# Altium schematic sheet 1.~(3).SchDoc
size 420 x 297 mm
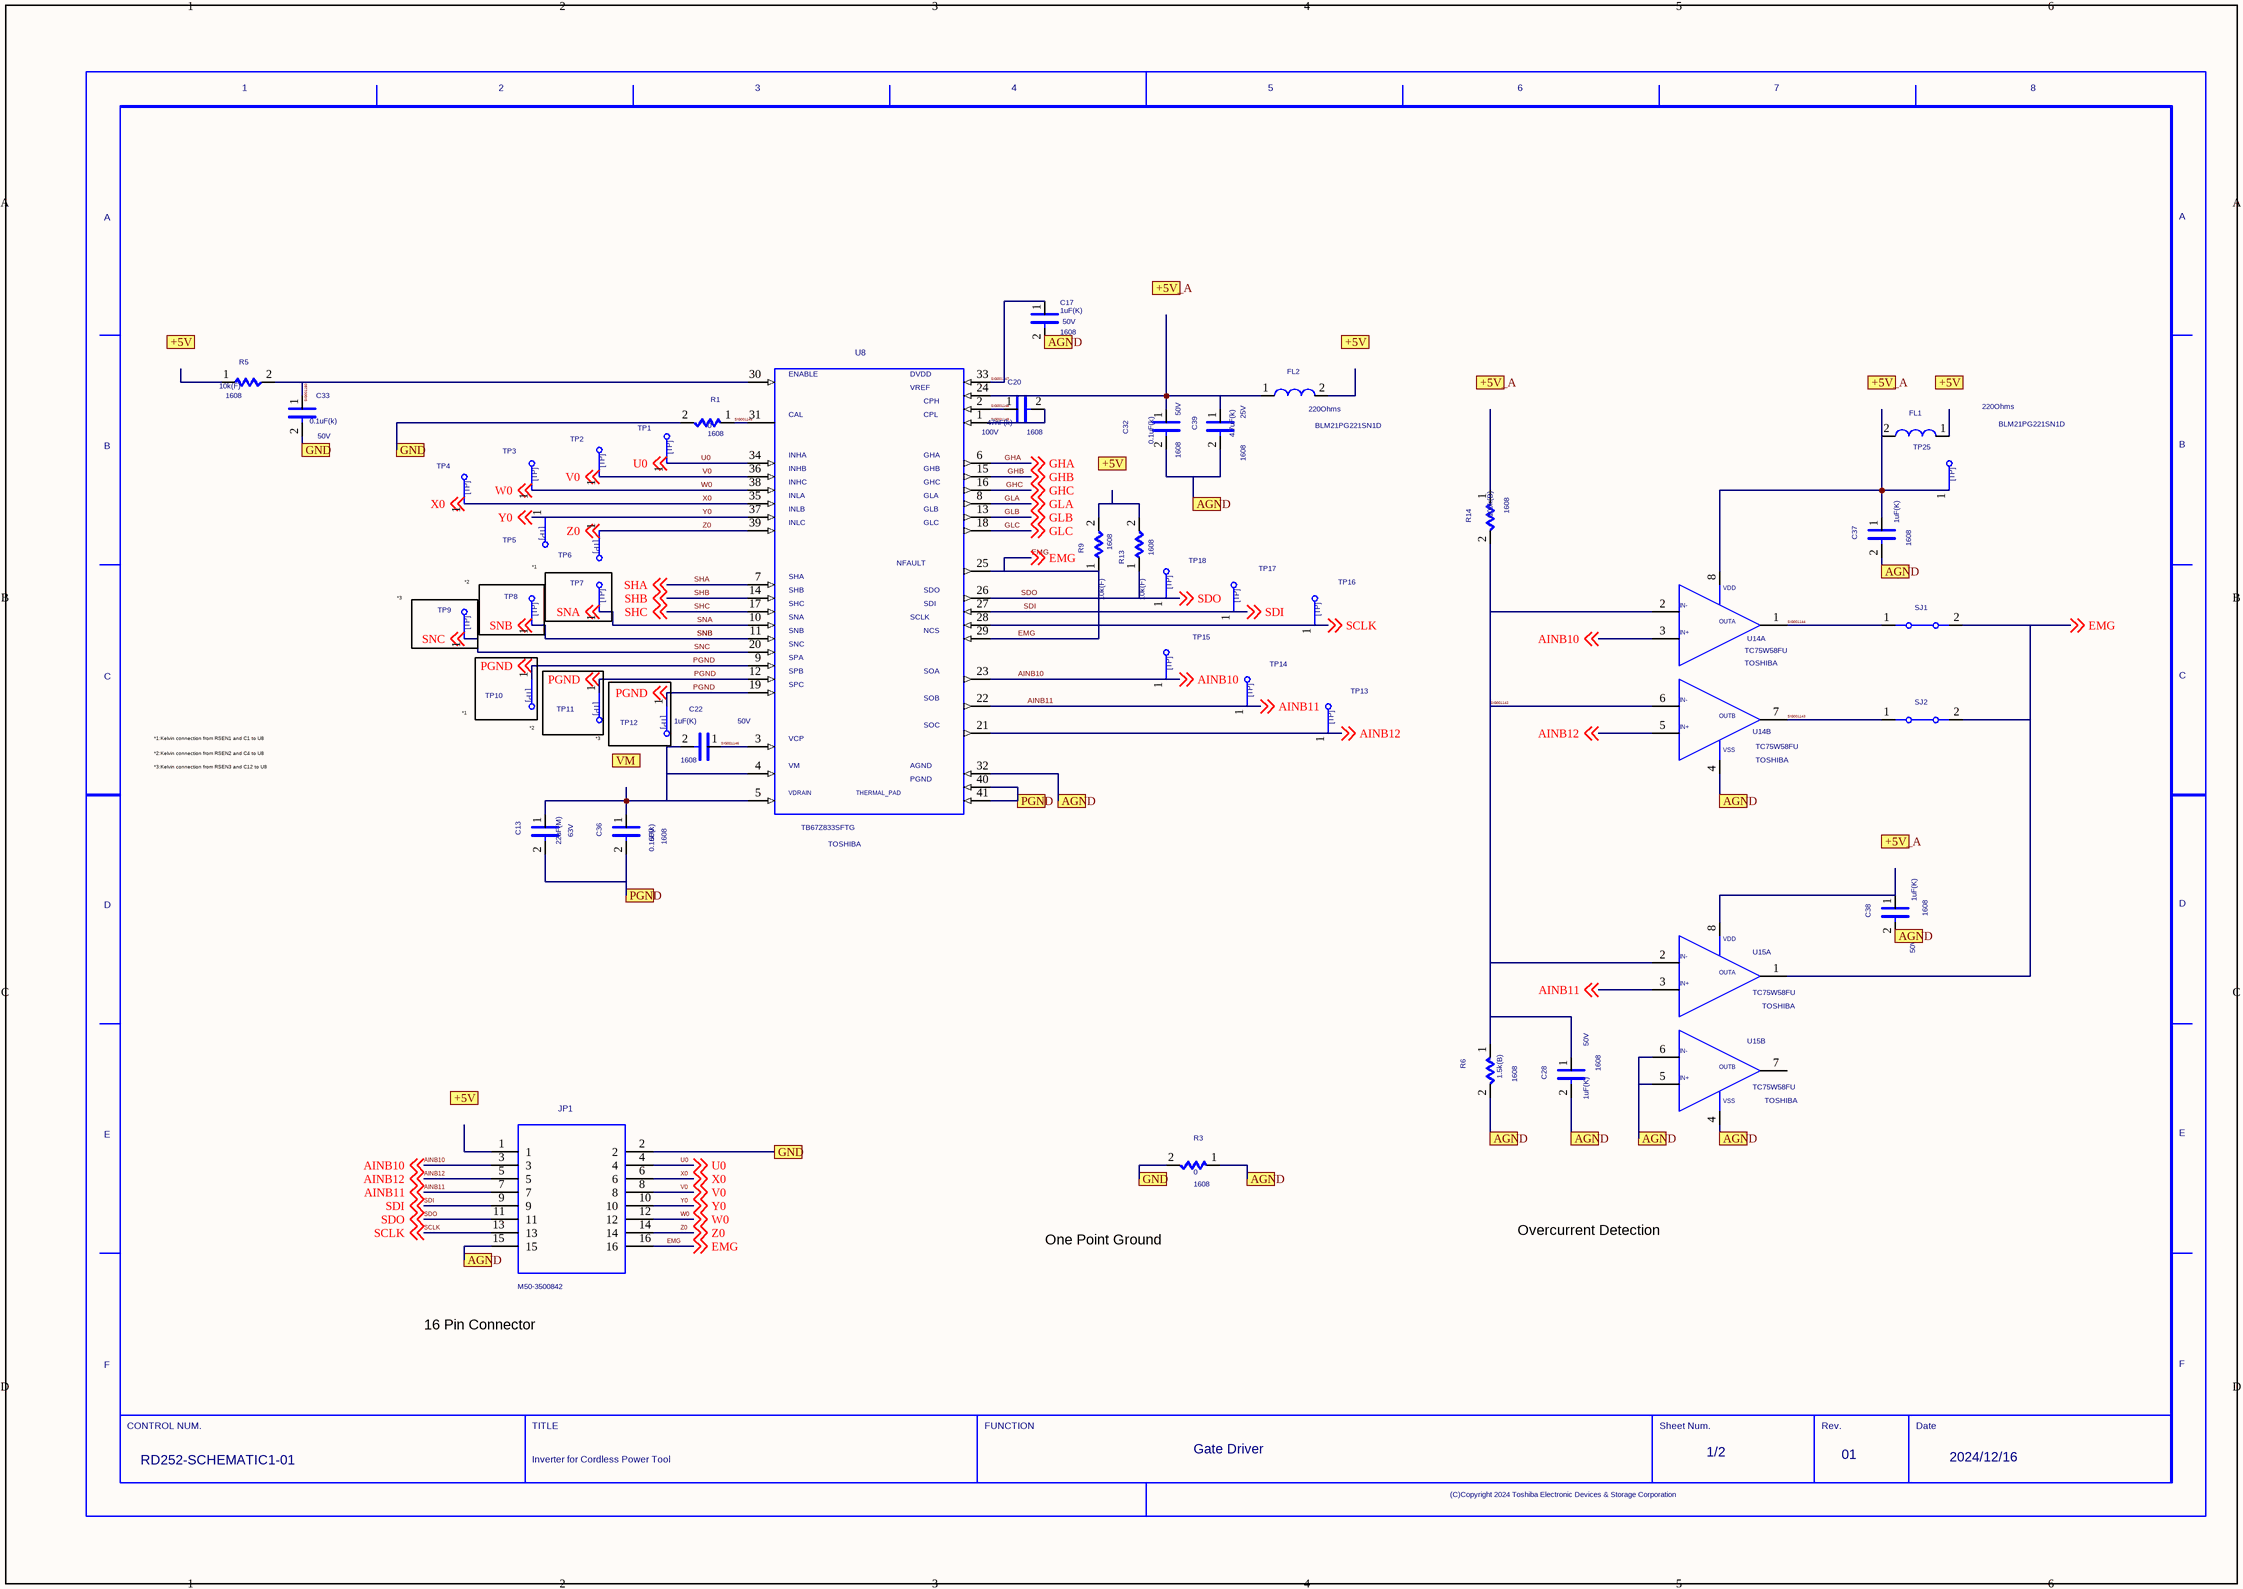
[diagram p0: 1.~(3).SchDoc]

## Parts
C13  VAL2: 63V  VAL1: 22uF(M)  (hidden comment: C)
C17  SIZECODESMD: 1608  VAL2: 50V  VAL1: 1uF(K)  (hidden comment: C)
C20  SIZECODESMD: 1608  VAL2: 100V  VAL1: 47nF(k)  (hidden comment: C)
C22  VAL2: 50V  SIZECODESMD: 1608  VAL1: 1uF(K)  (hidden comment: C)
C28  SIZECODESMD: 1608  VAL2: 50V  VAL1: 1uF(K)  (hidden comment: C)
C32  SIZECODESMD: 1608  VAL2: 50V  VAL1: 0.1uF(k)  (hidden comment: C)
C33  SIZECODESMD: 1608  VAL2: 50V  VAL1: 0.1uF(k)  (hidden comment: C)
C36  SIZECODESMD: 1608  VAL2: 50V  VAL1: 0.1uF(k)  (hidden comment: C)
C37  SIZECODESMD: 1608  VAL2: 50V  VAL1: 1uF(K)  (hidden comment: C)
C38  SIZECODESMD: 1608  VAL2: 50V  VAL1: 1uF(K)  (hidden comment: C)
C39  SIZECODESMD: 1608  VAL2: 25V  VAL1: 4.7uF(k)  (hidden comment: C)
FL1  VAL1: 220Ohms  VAL3: BLM21PG221SN1D  (hidden comment: L)
FL2  VAL1: 220Ohms  VAL3: BLM21PG221SN1D  (hidden comment: L)
JP1  VAL3: M50-3500842  [IDC16_1_27MM]  (hidden comment: CONN_16PINJ)
R1  SIZECODESMD: 1608  VAL1: 0  (hidden comment: R)
R3  SIZECODESMD: 1608  VAL1: 0  (hidden comment: R)
R5  SIZECODESMD: 1608  VAL1: 10k(F)  (hidden comment: R)
R6  SIZECODESMD: 1608  VAL1: 1.5k(B)  (hidden comment: R)
R9  SIZECODESMD: 1608  VAL1: 10k(F)  (hidden comment: R)
R13  SIZECODESMD: 1608  VAL1: 10k(F)  (hidden comment: R)
R14  SIZECODESMD: 1608  VAL1: 100k(B)  (hidden comment: R)
SJ1  JP  (value not drawn)
SJ2  JP  (value not drawn)
TP1  TP  (value not drawn)
TP2  TP  (value not drawn)
TP3  TP  (value not drawn)
TP4  TP  (value not drawn)
TP5  TP  (value not drawn)
TP6  TP  (value not drawn)
TP7  TP  (value not drawn)
TP8  TP  (value not drawn)
TP9  TP  (value not drawn)
TP10  TP  (value not drawn)
TP11  TP  (value not drawn)
TP12  TP  (value not drawn)
TP13  TP  (value not drawn)
TP14  TP  (value not drawn)
TP15  TP  (value not drawn)
TP16  TP  (value not drawn)
TP17  TP  (value not drawn)
TP18  TP  (value not drawn)
TP25  TP  (value not drawn)
U8  USERCOMPTEXT3: TOSHIBA  VAL3: TB67Z833SFTG  (hidden comment: DRV8323S)
U14  USERCOMPTEXT3: TOSHIBA  VAL3: TC75W58FU  (hidden comment: NA)  (parts A,B of 2)
U15  USERCOMPTEXT3: TOSHIBA  VAL3: TC75W58FU  (hidden comment: NA)  (parts A,B of 2)
U?  DATE: 2024/12/16  FUNCTION: Gate Driver  TITLE: Inverter for Cordless Power Tool  REVISION: 01  SHEETNUMBER: 1/2  DRAWINGNUMBER: RD252-SCHEMATIC1-01  (hidden comment: WAKU_DEF100)

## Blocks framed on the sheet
*2: TP9
*1: TP8

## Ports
+5V, +5V_A, AGND, GND, PGND, VM

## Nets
AGND: C17.2 C28.2 C32.2 C37.2 C38.2 C39.2 JP1.15 R3.1 R6.2 U8.32 U14.4 U15.4 U15.5 U15.6 ; port AGND
AINB10: JP1.3 TP15.1 U8.23 U14.3 ; off-sheet AINB10
AINB11: JP1.7 TP14.1 U8.22 U15.3 ; off-sheet AINB11
AINB12: JP1.5 TP13.1 U8.21 U14.5 ; off-sheet AINB12
EMG: JP1.16 R9.1 SJ1.2 SJ2.2 U8.25 U8.29 U15.1 ; off-sheet EMG
GHA: U8.6 ; off-sheet GHA
GHB: U8.15 ; off-sheet GHB
GHC: U8.16 ; off-sheet GHC
GLA: U8.8 ; off-sheet GLA
GLB: U8.13 ; off-sheet GLB
GLC: U8.18 ; off-sheet GLC
GND: C33.2 JP1.2 R1.2 R3.2 ; port GND
PGND: C13.2 C36.2 U8.40 U8.41 ; port PGND
PGND: TP10.1 TP11.1 TP12.1 U8.9 U8.12 U8.19 ; off-sheet PGND  [a separate net that carries the same name]
SCLK: JP1.13 TP16.1 U8.28 ; off-sheet SCLK
SDI: JP1.9 TP17.1 U8.27 ; off-sheet SDI
SDO: JP1.11 R13.1 TP18.1 U8.26 ; off-sheet SDO
SHA: U8.7 ; off-sheet SHA
SHB: U8.14 ; off-sheet SHB
SHC: U8.17 ; off-sheet SHC
SIG001142: C28.1 R6.1 R14.2 U14.2 U14.6 U15.2
SIG001143: SJ2.1 U14.7
SIG001144: SJ1.1 U14.1
SIG001145: R1.1 U8.31
SIG001146: C22.1 U8.3
SIG001147: C17.1 U8.33
SIG001148: C20.1 U8.2
SIG001149: C20.2 U8.1
SIG001150: C33.1 R5.2 U8.30
SNA: TP7.1 U8.10 ; off-sheet SNA
SNB: TP8.1 U8.11 ; off-sheet SNB
SNC: TP9.1 U8.20 ; off-sheet SNC
U0: JP1.4 TP1.1 U8.34 ; off-sheet U0
V0: JP1.8 TP2.1 U8.36 ; off-sheet V0
W0: JP1.12 TP3.1 U8.38 ; off-sheet W0
X0: JP1.6 TP4.1 U8.35 ; off-sheet X0
Y0: JP1.10 TP5.1 U8.37 ; off-sheet Y0
Z0: JP1.14 TP6.1 U8.39 ; off-sheet Z0
NetC13_1: C13.1 C22.2 C36.1 U8.4 U8.5
NetC32_1: C32.1 C39.1 FL2.1 U8.24
NetC37_1: C37.1 FL1.2 TP25.1 U14.8
NetC38_1: C38.1 U15.8
NetR9_2: R9.2 R13.2

Not connected (* = marked no-connect by the designer): FL1 1; FL2 2; JP1 1; R5 1; R14 1; U15 7

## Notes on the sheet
- *3
- *1
- *2
- *1:Kelvin connection from RSEN1 and C1 to U8
- *2:Kelvin connection from RSEN2 and C4 to U8
- *3:Kelvin connection from RSEN3 and C12 to U8
- (near TP11) *3
- One Point Ground
- Overcurrent Detection
- 16 Pin Connector

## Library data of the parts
C13 C17 C20 C22 C28 C32 C33 C36-C39 = C: TIME: 17:22:43; UPDATEUSER: t5459927; SAVECOUNT: 1; ORIGINALSYMBOLORIGIN: (-2540,5080)
FL1 FL2 = L: SAVECOUNT: 24; SAVEAREA0: -14227,-538,38802,29317; TIME: 11:19:06; UPDATEUSER: sptcae09; UPDATETIME: 15:04:42; COMP: 750315038; OriginalSymbolOrigin: (2540,5080)
JP1 = CONN_16PINJ_JP1: TIME: 10:49:14; UPDATEUSER: sptcae09; SAVECOUNT: 2; MP: TSM-108-01-L-DV; DEVICENAME: J; ORIGIN: Altium; MF: Samtec; GATENAME_1: A; OriginalSymbolOrigin: (0,0); INSTANCENAME: INS1151
R1 R3 = R: TIME: 17:22:43; UPDATEUSER: t5459927; SAVECOUNT: 1; ORIGINALSYMBOLORIGIN: (2540,2540); VAL2: 1A
R5 R9 R13 = R: TIME: 17:22:43; UPDATEUSER: t5459927; SAVECOUNT: 1; ORIGINALSYMBOLORIGIN: (2540,2540); VAL2: 330mW
R6 R14 = R: TIME: 17:22:43; UPDATEUSER: t5459927; SAVECOUNT: 1; ORIGINALSYMBOLORIGIN: (2540,2540); VAL2: 200mW
SJ1 SJ2 = JP: OriginalSymbolOrigin: (2540,5080); VAL3: Solder_Jumper; COMP: SJ; SAVECOUNT: 0
TP1-TP18 TP25 = TP: TIME: 16:12:21; UPDATEUSER: fukuda-y; UPDATETIME: 16:18:11; SAVECOUNT: 2; SAVEAREA0: -242,-92,12810,7836; OriginalSymbolOrigin: (0,7620)
U8 = TB67Z833SFTG_U8: TIME: 10:49:18; UPDATEUSER: t5459927; UPDATETIME: 19:51:29; SAVECOUNT: 3; MP: DRV8323SRTAT; ORIGIN: Altium; MF: Texas Instruments; GATENAME_1: G$1; OriginalSymbolOrigin: (0,0)
U14 U15 = TC75W58FU_1: TIME: 10:49:18; UPDATEUSER: t5459927; UPDATETIME: 18:58:17; SAVECOUNT: 8; GATENAME_1: G$1; SYMBOLNAME_1: TPH1R204PB; ORIGIN: Altium; OriginalSymbolOrigin: (0,0); CaptureCellPackProp: TC75W58FU_1A
U? = WAKU_DEF100_1: TIME: 14:30:25; UPDATEUSER: cae; UPDATETIME: 17:19:35; SAVECOUNT: 3; PLOTTIME: HH:MM; SAVEAREA0: -63393,-16950,474261,314592; ORIGINALSYMBOLORIGIN: (0,0); SHTSAVECOUNT: 90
